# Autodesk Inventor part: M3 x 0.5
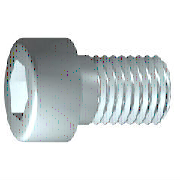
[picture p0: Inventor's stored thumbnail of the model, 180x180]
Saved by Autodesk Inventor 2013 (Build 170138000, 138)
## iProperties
IsCustomPart: 0
Created: 2015-10
Part Number: M3 x 0.5
Material: 강철, 연강
Description: 6각머리 태핑 나사
Document SubType Name: Modeling
Standard: KS B 1003
Designer: mdu
Standards Organization: KS
Language: ko-KR
Size Designation: M 3 x 12
Categories: <MemberInstance><Categories><Category DisplayName="조임쇠" InternalName="e4da775c-781d-43d5-af7c-5136215cf5a6" Mnemonic="FSTN"><Category DisplayName="볼트" InternalN
Density: 7.86 g/cm^3
Mass: 1.15208 g
Surface Area: 2.207 cm^2
Volume: 0.146575 cm^3
Author: mdu
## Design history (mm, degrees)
sketch "스케치1"
  geometry: L1 (-0.867, 0)-(12, 0); L2 (12, 0)-(12, 1.5); L3 (12, 1.5)-(1.25, 1.5); L4 (1.25, 1.5)-(0.943, 1.5); L5 (0.943, 1.5)-(0, 1.5); L6 (0, 1.5)-(0, 2.75); L7 (0, 2.75)-(-3, 2.75); L8 (-3, 2.75)-(-3, 1.443); L9 (-3, 1.443)-(-1.7, 1.443); L10 (-1.7, 1.443)-(-0.867, 0); L11 (-6, 0)-(15, 0) reference; L12 (0, -0.55)-(0, 3.3) reference; L13 (1.25, 1.5)-(0, 1.5)
  constraints: 22 end point, 6 parallel, 2 collinear, 2 perpendicular, 1 horizontal, 1 point on line
  dimensions: "d1" = 10.75 distance from line of L3.end L2 (= GEL); "d2" = 0.30683 distance of L4.end L3.end (computed from GAL); "d3" = 3 distance between parallel lines of L8 L6 (= KOH); "d4" = 1.3 distance of L8.end L9.end (= INTI); "d5" = 60 deg angle of L10 L1; "d6" = 3 diameter of L3 L1 (= GD); "d7" = 3 diameter of L5 L1 (= BDM); "d8" = 2.88675 diameter of L9 L1 (= 1.1547 x SW); "d9" = 5.5 diameter of L7 L1 (= KOD); "d26" = 12 distance between parallel lines of L12 L2 (= NLG)
revolve "본체" sketch "스케치1" stored, may be unused: angle "d10" = 90 deg
sketch "스케치2"
  geometry: L1 (0, -3.85)-(0, 3.85) reference; L2 (-3.85, 0)-(3.85, 0) reference; L3 (1.443, 0)-(0.722, -1.25); L4 (0.722, -1.25)-(-0.722, -1.25); L5 (-0.722, -1.25)-(-1.443, 0); L6 (-1.443, 0)-(-0.722, 1.25); L7 (-0.722, 1.25)-(0.722, 1.25); L8 (0.722, 1.25)-(1.443, 0); 2 further points
  constraints: 12 end point, 1 coincident, 1 horizontal alignment, 1 point on line, 12 other
extrude "슬롯" join sketch "스케치2" stored distance "d11" = 10; taper "d12" = 0 deg
workplane "Work Plane1"
fillet "Fillet2" dims "d30" = 0.1 (= R)
body "Solid1"
fillet "모깎기1" dims "d17" = 0.3 (= RR)
feature "스레드" dims "d13" = 10.75 (= GEL), "d14" = 0
chamfer "모따기1" distance "d15" = 0.30673 (= -0.5 x SPD + 0.5 x GD); stored, may be unused: second distance "d16" = 0.30673 (= GUL), angle "d27" = 45 deg
other parameters: "GD" = 3 (= NND) [user parameter; used in 2 equation terms], "NLG" = 12 [user parameter; used in 1 equation term], "GEL" = 10.75 [user parameter; used in 2 equation terms], "KOD" = 5.5 [user parameter; used in 1 equation term], "KOH" = 3 [user parameter; used in 1 equation term], "INTI" = 1.3 [user parameter; used in 1 equation term], "GAL" = 0.30673 (= 0.61345 x PTC) [user parameter; used in 1 equation term], "GUL" = 0.30673 (= 0.61345 x PTC) [user parameter; used in 1 equation term], "BDM" = 3 (= NND) [user parameter; used in 1 equation term], "SW" = 2.5 [user parameter; used in 2 equation terms], "RR" = 0.3 [user parameter; used in 1 equation term], "SPD" = 2.38655 (= NND - 1.2269 x PTC) [user parameter; used in 1 equation term], "d19" = 0, "d28" = 0, "d29" = 0, "R" = 0.1 [user parameter; used in 1 equation term], "PHH" = 0.1 [user parameter], "GD1" = 2.38655 (= THREADDIA - 1.2269 x PTC) [user parameter], "THREADDIA" = 3 [user parameter; used in 1 equation term], "FAWI" = 45 deg [user parameter], "PTC" = 0.5 [user parameter; used in 5 equation terms], "NND" = 3 [user parameter; used in 3 equation terms], "TOA" = 30 deg [user parameter], "E0" = 2.8875 (= 1.155 x SW) [user parameter]
